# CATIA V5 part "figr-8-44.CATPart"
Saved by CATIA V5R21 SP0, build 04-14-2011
Part number: Part1
Bounding box of the stored display mesh (mm): x -50 to 50, y -50 to 50, z 0 to 25
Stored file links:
  D:\CATIA V5R21 E-RESOURCES\CATIA-V5R21\catia-v5r21-prt\c08-catia-v5r20-prt\c08-catia-v5r21-figr-8-44.CATPart
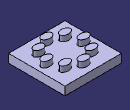
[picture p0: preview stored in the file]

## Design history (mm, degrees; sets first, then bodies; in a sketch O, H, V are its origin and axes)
Body1 (main body)
  Sketch1 on xy-plane, origin (0, 0, 0), H (1, 0, 0), V (0, 1, 0)
    line L1 (-50, 50) -> (50, 50)
    line L2 (50, 50) -> (50, -50)
    line L3 (50, -50) -> (-50, -50)
    line L4 (-50, -50) -> (-50, 50)
    axis line L5 (50, -50) -> (-50, 50)
    length L2 = 100
    length L3 = 100
    horizontal: L1 H, L3 H
    vertical: L2 V, L4 V
    midpoint: L5 O
  Pad1: profile Sketch1, direction (0, 0, 1), length 15
  Sketch2 on face of Pad1, origin (0, 0, 15), H (1, 0, 0), V (0, 1, 0)
    point P1 (0, -32.9864)
    ellipse A1 centre (0, -32.9864) semi-axes 9.9006, 6.5465 rotation 0
    point P2 (0, -26.4399)
    coincidence: P1 V, P2 V, A1 P2
  Pad2: profile Sketch2, direction (0, 0, 1), length 10
  CircPattern1: of Pad2, instances 8, angular step 45 {= 360.0*1 deg/CircPattern1.AngularNumber}, axis from edge of Sketch3
  Sketch3 on yz-plane, origin (0, 0, 0), H (0, 1, 0), V (0, 0, 1)
    line L1 (0, 0) -> (0, 18.4864)
    vertical: L1 V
